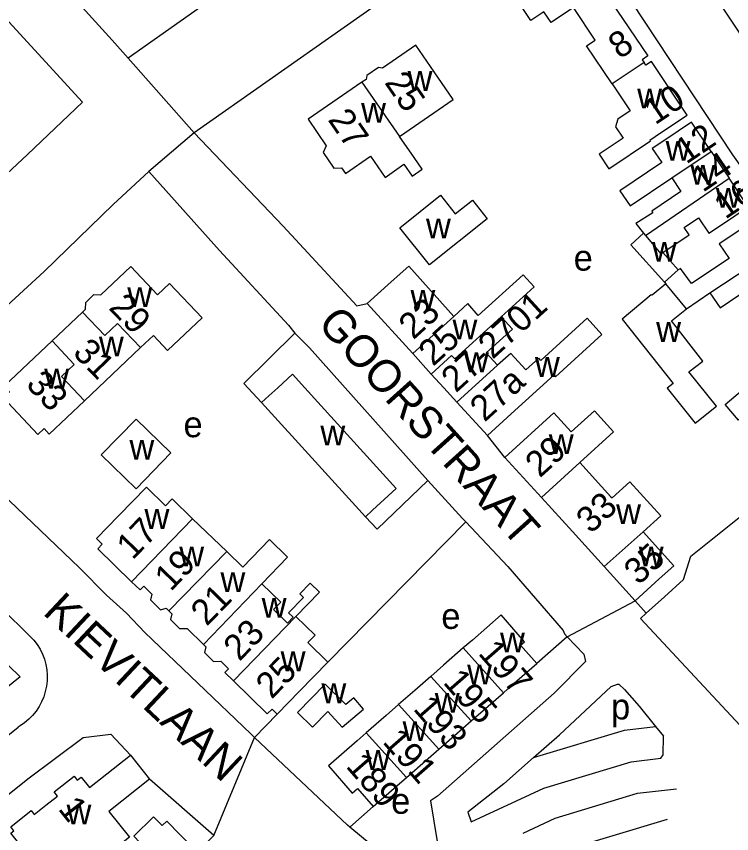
# Model space of a CAD drawing. Extents: x 161775 to 163181, y 382878 to 383925.
# Drawn here: x 162768.1 to 162879.2, y 383680.7 to 383807.7 of the extents above; entities that cross this region are included whole.
import ezdxf

# ---------------------------------------------------------------- set-up
doc = ezdxf.new("R2010")
doc.units = 0
for name, color, linetype in [('BLT_Basislijn', 7, 'Continuous'), ('BLT_Bebouwing', 7, 'Continuous'), ('BLT_Centroide', 7, 'Continuous'), ('BLT_Huisnummer', 7, 'Continuous'), ('BLT_Huisnummer_ tussenligend', 7, 'Continuous'), ('BLT_Huisnummer_reeks', 7, 'Continuous'), ('BLT_Onderverdeling_panden', 7, 'Continuous'), ('BLT_Straatnaam', 7, 'Continuous'), ('BLT_Vlakafsluiter', 7, 'Continuous')]:
    doc.layers.add(name, color=color, linetype=linetype)

msp = doc.modelspace()

# ---------------------------------------------------------------- linework, layer by layer
at = {"layer": 'BLT_Basislijn'}
for p, q in [((162844.02, 383739.18), (162841.29, 383742.56)), ((162745.28, 383735.94), (162770.85, 383710.77)), ((162837.92, 383729.15), (162816.52, 383707.36)), ((162768.72, 383705.07), (162755.35, 383717.89)), ((162865.98, 383714.96), (162864.26, 383716.91)), ((162853.7, 383711.28), (162848.95, 383707.13)), ((162768.72, 383705.07), (162747.45, 383688.05)), ((162805.12, 383695.66), (162808.63, 383699.27)), ((162712.92, 383652.82), (162768.39, 383697.27)), ((162798.8, 383680.44), (162788.81, 383689.19)), ((162823.55, 383684.9), (162819.92, 383681.73)), ((162850.56, 383677.36), (162869.25, 383682.97))]:
    msp.add_line(p, q, dxfattribs=at)
for points in [[(162703.8, 383876.24), (162706.56, 383872.66), (162712.77, 383866.28), (162715.7, 383862.52), (162731.68, 383845.59), (162737.91, 383838.46), (162738.87, 383837.6), (162741.07, 383834.89), (162742.28, 383833.77), (162778.38, 383794.39)], [(162785.46, 383801.22), (162782.97, 383804.02), (162724.1, 383868.83)], [(162843.74, 383842.12), (162840.57, 383839.67), (162820.94, 383826.15), (162818.33, 383824.15), (162805.7, 383815.51), (162785.46, 383801.22)], [(162624.33, 383833.08), (162626.77, 383831.18), (162649.91, 383815.03), (162662.77, 383805.45), (162714.41, 383769.18), (162720.06, 383764.71), (162723.13, 383762.72), (162734.54, 383754.59), (162735.88, 383754.49), (162750.82, 383768.72), (162752.99, 383770.53), (162769.85, 383786.24), (162778.38, 383794.39)], [(162862.81, 383831.51), (162863.53, 383830.66), (162880.56, 383804.94)], [(162851.26, 383828.4), (162847.79, 383826.29), (162838.22, 383819.22), (162830.67, 383814.23), (162795.74, 383789.61)], [(162851.26, 383828.4), (162861.71, 383812.99), (162879.37, 383786.19), (162884.88, 383778.46), (162900.37, 383755.32), (162903.33, 383751.28), (162915.73, 383733.22)], [(162795.74, 383789.61), (162809.57, 383775.09), (162821.01, 383762.71), (162822.63, 383763.09)], [(162805.12, 383695.66), (162804.54, 383696.2), (162788.08, 383711.95), (162785.2, 383714.99), (162782.12, 383717.76), (162777.9, 383722), (162751.13, 383747.61), (162751.03, 383747.93), (162760.8, 383757.39), (162772.45, 383768.09), (162783.14, 383778.49), (162788.71, 383783.59)], [(162788.71, 383783.59), (162799.68, 383771.31), (162810.39, 383759.71), (162811.35, 383758.46)], [(162806.21, 383747.71), (162803.43, 383750.68), (162811.35, 383758.46)], [(162811.35, 383758.46), (162813.67, 383756.2), (162832.06, 383735.59)], [(162822.33, 383729.96), (162824.19, 383728.03), (162832.06, 383735.59)], [(162837.92, 383729.15), (162837.44, 383729.66), (162832.06, 383735.59)], [(162837.92, 383729.15), (162844.46, 383722.2), (162853.05, 383712.28), (162853.25, 383711.74), (162853.7, 383711.28)], [(162853.7, 383711.28), (162856.29, 383708.62), (162856.52, 383707.48), (162851.68, 383702.53), (162833.55, 383686.54), (162832.46, 383685.79), (162833.5, 383679.47), (162828.96, 383677.8), (162826.05, 383677.67), (162823.21, 383678.95), (162819.92, 383681.73)], [(162770.85, 383710.77), (162771.35, 383710.1), (162771.8, 383709.37), (162772.17, 383708.61), (162772.46, 383707.82), (162772.69, 383707), (162772.83, 383706.16), (162772.9, 383705.32), (162772.88, 383704.47), (162772.79, 383703.63), (162772.61, 383702.8), (162772.36, 383701.99), (162772.03, 383701.21), (162771.64, 383700.46), (162771.17, 383699.75), (162770.64, 383699.09), (162770.04, 383698.49), (162769.4, 383697.94), (162768.7, 383697.45), (162768.39, 383697.27)], [(162848.46, 383692.52), (162852.49, 383696.08), (162860.53, 383703.55), (162861.48, 383703.93), (162861.7, 383703.96), (162862.6, 383703.1), (162864.87, 383700.54), (162867.43, 383697.37)], [(162848.46, 383692.52), (162862.58, 383696.81), (162867.43, 383697.37)], [(162867.43, 383697.37), (162868.64, 383695.86)], [(162626.44, 383574.02), (162637.05, 383582.56), (162638.49, 383583.91), (162653.34, 383595.54), (162654.82, 383596.89), (162659.77, 383600.62), (162668.36, 383607.94), (162675.68, 383613.76), (162684.73, 383621.34), (162722.73, 383651.25), (162727.65, 383655.52), (162732.82, 383659.35), (162734.51, 383660.88), (162769.87, 383689.21), (162778.48, 383695.66), (162782.77, 383696.15), (162785.83, 383692.92)], [(162819.92, 383681.73), (162819.56, 383682.03), (162805.12, 383695.66)], [(162868.25, 383692.44), (162868.59, 383692.95), (162868.64, 383695.86)], [(162838.76, 383682.55), (162850.04, 383687.77), (162863.61, 383691.89), (162868.25, 383692.44)], [(162843.83, 383688.42), (162848.46, 383692.52)], [(162843.83, 383688.42), (162838.27, 383684.03), (162838.76, 383682.55)], [(162846.83, 383680.77), (162851.83, 383683.09), (162864.63, 383686.98), (162870.66, 383687.68)]]:
    msp.add_lwpolyline(points, dxfattribs=at)
at = {"layer": 'BLT_Bebouwing'}
for p, q in [((162876.05, 383786.72), (162878.84, 383782.56)), ((162863.57, 383772.22), (162865.56, 383774.04)), ((162868.52, 383771.02), (162870.95, 383768.33)), ((162822.63, 383763.09), (162829.68, 383755.3)), ((162773.65, 383757.27), (162778.41, 383761.77)), ((162829.68, 383755.3), (162832.56, 383752.13)), ((162806.21, 383747.71), (162822.33, 383729.96)), ((162836.55, 383747.74), (162841.29, 383742.56)), ((162849.67, 383732.96), (162844.02, 383739.18)), ((162855.65, 383738.39), (162860.49, 383733.07)), ((162854.5, 383727.65), (162849.67, 383732.96)), ((162859.44, 383722.22), (162854.5, 383727.65)), ((162864.26, 383716.91), (162859.44, 383722.22)), ((162838.95, 383710.79), (162837.55, 383709.56)), ((162837.55, 383709.56), (162834.48, 383706.88)), ((162834.48, 383706.88), (162832.51, 383705.15)), ((162845.1, 383703.76), (162848.95, 383707.13)), ((162832.51, 383705.15), (162830.01, 383702.96)), ((162843.78, 383702.61), (162845.1, 383703.76)), ((162830.01, 383702.96), (162827.5, 383700.77)), ((162840.63, 383699.85), (162843.78, 383702.61)), ((162827.5, 383700.77), (162825.54, 383699.05)), ((162838.76, 383698.22), (162840.63, 383699.85)), ((162825.54, 383699.05), (162822.48, 383696.37)), ((162836.16, 383695.94), (162838.76, 383698.22)), ((162822.48, 383696.37), (162821.07, 383695.14)), ((162833.74, 383693.82), (162836.16, 383695.94)), ((162831.69, 383692.03), (162833.74, 383693.82)), ((162785.83, 383692.92), (162788.81, 383689.19)), ((162828.71, 383689.42), (162831.69, 383692.03)), ((162827.22, 383688.11), (162828.71, 383689.42)), ((162823.55, 383684.9), (162827.22, 383688.11))]:
    msp.add_line(p, q, dxfattribs=at)
for points in [[(162860.66, 383797.25), (162856.7, 383803.15), (162858.03, 383804.04), (162854.65, 383809.08), (162851.2, 383806.76), (162850.08, 383808.42), (162848.05, 383807.06), (162845.06, 383811.52), (162842.27, 383815.67), (162849.89, 383820.78), (162851.18, 383818.84), (162852.52, 383819.74), (162857.54, 383812.25), (162858.57, 383812.94), (162866.2, 383801.56), (162865.34, 383800.98), (162865.62, 383800.55)], [(162827.64, 383789.07), (162835.98, 383794.8), (162833.02, 383799.1), (162830.19, 383803.22), (162824.98, 383799.64), (162824.35, 383799.76), (162822.54, 383798.52), (162822.43, 383797.92), (162821.79, 383797.48)], [(162860.66, 383797.25), (162863.49, 383793.04), (162861.54, 383791.73), (162861.18, 383790.55), (162862.37, 383788.78), (162858.64, 383786.29), (162860.16, 383784.03), (162866.61, 383788.35), (162866.52, 383788.49), (162868.17, 383789.59), (162872.32, 383792.38), (162866.78, 383800.68), (162865.91, 383800.11), (162865.62, 383800.55)], [(162821.79, 383797.48), (162813.43, 383791.73), (162816.26, 383787.62), (162815.75, 383786.54), (162817.42, 383784.1), (162818.62, 383784.19), (162819.24, 383783.29), (162823.13, 383785.97), (162825.4, 383782.67), (162828.31, 383784.75), (162829.61, 383782.87), (162831.17, 383783.95), (162829.91, 383785.77), (162827.64, 383789.07)], [(162876.05, 383786.72), (162872.99, 383791.28), (162868.84, 383788.5), (162866.91, 383787.18), (162868.4, 383784.99), (162861.88, 383780.62), (162863.45, 383778.27), (162869.93, 383782.61)], [(162869.93, 383782.61), (162871.35, 383780.49), (162866.81, 383777.44), (162866.99, 383777.17), (162864.33, 383775.52), (162865.56, 383774.04)], [(162868.52, 383771.02), (162872.62, 383773.76), (162871.84, 383774.91), (162874.09, 383776.42), (162875.7, 383774.02), (162877.66, 383775.34), (162881.82, 383778.12), (162878.84, 383782.56)], [(162886.2, 383771.65), (162884.86, 383773.64), (162885.38, 383773.99), (162883.9, 383776.21), (162883.37, 383775.85), (162883.11, 383776.24), (162878.96, 383773.45), (162877.32, 383772.37), (162878.83, 383770.09), (162873.01, 383766.19), (162871.3, 383768.54), (162870.95, 383768.33)], [(162863.57, 383772.22), (162868.82, 383766.39)], [(162875.87, 383764.73), (162877.43, 383762.4), (162881.98, 383765.46), (162883.49, 383763.22), (162885.11, 383764.29), (162889.27, 383767.08), (162886.2, 383771.65)], [(162778.41, 383761.77), (162778.86, 383762.2), (162778.89, 383763.27), (162780.17, 383764.48), (162781.24, 383764.45), (162785.88, 383768.84), (162790.04, 383764.43), (162791.91, 383766.2), (162796.96, 383760.89), (162791.59, 383755.81), (162789.4, 383758.12), (162787.42, 383756.24)], [(162836.05, 383761.09), (162829.07, 383768.92), (162826.34, 383766.44), (162822.63, 383763.09)], [(162843.44, 383761.02), (162848.55, 383765.67), (162846.84, 383767.56), (162839.88, 383761.25), (162838.23, 383763.08), (162836.05, 383761.09)], [(162869.03, 383766.14), (162866.89, 383764.38), (162866.74, 383764.42), (162862.25, 383760.68), (162870.17, 383750.68), (162869.23, 383749.93), (162873.57, 383744.5), (162876.86, 383747.13), (162872.6, 383752.46), (162874.77, 383754.15), (162869.9, 383760.38), (162872.2, 383762.26)], [(162868.82, 383766.39), (162869.03, 383766.14)], [(162872.2, 383762.26), (162875.87, 383764.73)], [(162843.44, 383761.02), (162845.18, 383759.1), (162843.16, 383757.27), (162841.12, 383755.42), (162842.87, 383753.49)], [(162841.29, 383742.56), (162844.99, 383745.93), (162849.45, 383750), (162851.64, 383751.99), (162851.89, 383751.72), (162859.09, 383758.25), (162856.77, 383760.8), (162849.58, 383754.26), (162849.27, 383754.61), (162847.24, 383752.77), (162844.91, 383755.34), (162842.87, 383753.49)], [(162778.68, 383747.99), (162773.21, 383742.81), (162772.42, 383743.65), (162771.47, 383742.76), (162766.08, 383748.47), (162767.03, 383749.36), (162766.42, 383750), (162766.2, 383750.23), (162773.65, 383757.27)], [(162778.68, 383747.99), (162780.8, 383750), (162787.42, 383756.24)], [(162887.66, 383745.68), (162885.02, 383748.94), (162880.31, 383744.94), (162878.22, 383747.41), (162886.6, 383754.51), (162887.68, 383755.24), (162887.46, 383755.36)], [(162822.33, 383729.96), (162823.44, 383730.96), (162827.14, 383734.33), (162812.92, 383750), (162811.02, 383752.09), (162808.72, 383750), (162807.32, 383748.73), (162806.21, 383747.71)], [(162832.56, 383752.13), (162834.5, 383749.99), (162836.55, 383747.74)], [(162844.02, 383739.18), (162851.62, 383746.1), (162854.32, 383743.13), (162857.92, 383746.41), (162860.89, 383743.15), (162855.65, 383738.39)], [(162860.49, 383733.07), (162860.67, 383732.87), (162863.42, 383735.38), (162868.22, 383730.09), (162865.47, 383727.59)], [(162795.48, 383729.63), (162792.31, 383732.72), (162791.28, 383731.66), (162788.32, 383734.54), (162784.04, 383730.15), (162780.55, 383726.57), (162781.46, 383725.68), (162780.77, 383724.97), (162786.02, 383719.86)], [(162865.98, 383714.96), (162868.78, 383717.51), (162871.76, 383720.22), (162872.87, 383723.81), (162882.71, 383731.71)], [(162795.48, 383729.63), (162800.81, 383724.55)], [(162865.47, 383727.59), (162870.24, 383722.35), (162867.96, 383720.28), (162864.26, 383716.91)], [(162800.81, 383724.55), (162803.27, 383722.14), (162807.43, 383726.4), (162810.24, 383723.65), (162806.23, 383719.55)], [(162786.02, 383719.86), (162787.34, 383718.57), (162787.89, 383719.14), (162789.16, 383717.91), (162788.93, 383717.02), (162790.48, 383715.5), (162791.39, 383715.76), (162791.82, 383715.33)], [(162806.23, 383719.55), (162809.18, 383716.66), (162808.07, 383715.52), (162810.21, 383713.43), (162811.1, 383714.35), (162810.4, 383715.03), (162812.72, 383717.4), (162812.14, 383717.97), (162813.77, 383719.64), (162815.22, 383718.23), (162811.54, 383714.46)], [(162791.82, 383715.33), (162792.29, 383714.88), (162792.06, 383713.97), (162793.48, 383712.58), (162794.64, 383712.59), (162797.21, 383710.08)], [(162811.54, 383714.46), (162814.51, 383711.56), (162813.39, 383710.41), (162816.52, 383707.36)], [(162848.95, 383707.13), (162846.45, 383709.98), (162847.07, 383710.52), (162843.42, 383714.7), (162838.95, 383710.79)], [(162883.88, 383694.79), (162883.34, 383694.51), (162865.08, 383714.14), (162865.98, 383714.96)], [(162797.21, 383710.08), (162797.57, 383709.74), (162797.34, 383708.83), (162798.74, 383707.47), (162799.9, 383707.49), (162801.07, 383706.34), (162800.49, 383705.74), (162801.84, 383704.43)], [(162808.63, 383699.27), (162812.12, 383702.85), (162816.52, 383707.36)], [(162801.84, 383704.43), (162807.09, 383699.3), (162807.83, 383700.05), (162808.63, 383699.27)], [(162811.8, 383699.51), (162814.14, 383697.25), (162816.48, 383699.67), (162818.74, 383697.25), (162822.02, 383700.06), (162820.53, 383701.81), (162819.31, 383700.77), (162816.09, 383703.91), (162811.8, 383699.51)], [(162821.07, 383695.14), (162816.6, 383691.23), (162820.3, 383687), (162821.1, 383687.7), (162823.55, 383684.9)], [(162772.7, 383685.11), (162774.51, 383686.55), (162774.01, 383687.18), (162777.07, 383689.62), (162777.56, 383689.02), (162778.17, 383689.5), (162779.48, 383687.86), (162785.83, 383692.92)], [(162788.81, 383689.19), (162782.49, 383684.15), (162785.68, 383680.16), (162781.77, 383677.04), (162780.16, 383675.75)], [(162770.37, 383669.19), (162767.38, 383673.06), (162771.11, 383675.95), (162767.27, 383680.77), (162767.74, 383681.15), (162767.24, 383681.78), (162770.39, 383684.29), (162770.89, 383683.67), (162772.7, 383685.11)], [(162798.8, 383680.44), (162797.58, 383679.25), (162799.12, 383677.68), (162797.69, 383676.28), (162791.47, 383682.65), (162790.75, 383681.95), (162789.43, 383683.31), (162786.37, 383680.32), (162802.45, 383663.3), (162803.49, 383664.28), (162805.75, 383661.89)]]:
    msp.add_lwpolyline(points, dxfattribs=at)
for points in [[(162827.68, 383774.87), (162834.02, 383779.91), (162836.3, 383777.04), (162838.95, 383779.15), (162841.27, 383776.23), (162832.28, 383769.09)], [(162786.71, 383745.13), (162792.11, 383739.86), (162786.7, 383734.31), (162781.29, 383739.58)]]:
    msp.add_lwpolyline(points, close=True, dxfattribs=at)
at = {"layer": 'BLT_Onderverdeling_panden'}
for p, q in [((162865.62, 383800.55), (162860.66, 383797.25)), ((162821.79, 383797.48), (162827.64, 383789.07)), ((162869.93, 383782.61), (162876.05, 383786.72)), ((162865.87, 383773.66), (162878.84, 383782.56)), ((162865.56, 383774.04), (162865.87, 383773.66)), ((162875.87, 383764.73), (162886.2, 383771.65)), ((162868.82, 383766.39), (162870.95, 383768.33)), ((162872.2, 383762.26), (162869.03, 383766.14)), ((162836.05, 383761.09), (162829.68, 383755.3)), ((162842.87, 383753.49), (162836.55, 383747.74)), ((162849.67, 383732.96), (162855.65, 383738.39)), ((162795.48, 383729.63), (162786.02, 383719.86)), ((162859.44, 383722.22), (162865.47, 383727.59)), ((162800.81, 383724.55), (162791.82, 383715.33)), ((162806.23, 383719.55), (162797.21, 383710.08)), ((162811.54, 383714.46), (162801.84, 383704.43)), ((162843.78, 383702.61), (162837.55, 383709.56)), ((162838.76, 383698.22), (162832.51, 383705.15)), ((162833.74, 383693.82), (162827.5, 383700.77)), ((162828.71, 383689.42), (162822.48, 383696.37))]:
    msp.add_line(p, q, dxfattribs=at)
for points in [[(162865.87, 383773.66), (162868.23, 383770.82), (162868.52, 383771.02)], [(162787.42, 383756.24), (162783.82, 383759.97), (162781.86, 383758.12), (162778.41, 383761.77)], [(162843.44, 383761.02), (162836.23, 383754.47), (162835.73, 383755.02), (162832.56, 383752.13)], [(162778.68, 383747.99), (162775.15, 383751.75), (162777.11, 383753.61), (162773.65, 383757.27)]]:
    msp.add_lwpolyline(points, dxfattribs=at)
at = {"layer": 'BLT_Vlakafsluiter'}
for p, q in [((162785.46, 383801.22), (162795.74, 383789.61)), ((162795.74, 383789.61), (162788.71, 383783.59)), ((162853.7, 383711.28), (162864.26, 383716.91)), ((162798.8, 383680.44), (162805.12, 383695.66))]:
    msp.add_line(p, q, dxfattribs=at)

# ---------------------------------------------------------------- texts
at = {"layer": 'BLT_Centroide'}
for s, p in [('w', (162828.89, 383796.14)), ('w', (162864.56, 383793.41)), ('w', (162821.67, 383791.19)), ('w', (162868.97, 383785.28)), ('w', (162872.83, 383781.55)), ('w', (162876.78, 383777.97)), ('w', (162831.75, 383773.2)), ('w', (162866.85, 383769.59)), ('e', (162854.69, 383768.2)), ('w', (162785.35, 383762.53)), ('w', (162829.34, 383762.14)), ('w', (162835.87, 383757.53)), ('w', (162867.51, 383757.13)), ('w', (162780.94, 383754.88)), ('w', (162837.65, 383752.42)), ('w', (162848.67, 383751.69)), ('w', (162772.44, 383749.88)), ('e', (162794.08, 383742.31)), ('w', (162815.34, 383741.03)), ('w', (162785.68, 383738.83)), ('w', (162850.83, 383739.69)), ('w', (162861.29, 383728.81)), ('w', (162788.02, 383728.06)), ('w', (162793.42, 383722.23)), ('w', (162864.8, 383722.25)), ('w', (162799.82, 383718.25)), ('w', (162806.22, 383714.25)), ('e', (162834.13, 383712.52)), ('w', (162843.25, 383708.88)), ('w', (162809.17, 383705.94)), ('w', (162838.14, 383703.91)), ('w', (162815.5, 383700.98)), ('w', (162833.12, 383699.48)), ('p', (162860.5, 383698.45)), ('w', (162828.11, 383695.09)), ('w', (162822.37, 383690.62)), ('e', (162826.34, 383683.79)), ('w', (162775.91, 383682.16))]:
    msp.add_text(s, height=4, dxfattribs=at).set_placement(p)
at = {"layer": 'BLT_Huisnummer'}
for s, rotation, p in [('25', 304.5232, (162825.21, 383797.42)), ('10', 33.8517, (162867.35, 383790.76)), ('27', 304.5174, (162816.41, 383791.65)), ('12', 33.8517, (162872.18, 383784.66)), ('14', 33.8427, (162874.75, 383780.28)), ('16', 33.8427, (162878.25, 383776.09)), ('29', 314.0783, (162782.32, 383762.32)), ('23', 42.2845, (162829.78, 383757.35)), ('33', 313.3733, (162769.45, 383750.39)), ('27a', 42.3739, (162840.85, 383744.56)), ('29', 42.2799, (162849.43, 383735.89)), ('17', 45.7212, (162786.15, 383723.11)), ('35', 42.2852, (162864.77, 383719.21)), ('21', 45.7199, (162797.68, 383712.83)), ('197', 311.1877, (162839.73, 383708.67)), ('25', 45.7129, (162807.78, 383701.5)), ('193', 311.1917, (162829.63, 383700.04)), ('189', 311.1898, (162819.17, 383691.12)), ('1', 308.5813, (162774.48, 383684.53))]:
    msp.add_text(s, height=4, rotation=rotation, dxfattribs=at).set_placement(p)
at = {"layer": 'BLT_Huisnummer_ tussenligend'}
for s, rotation, p in [('25', 42.1781, (162832.85, 383753.22)), ('31', 314.0783, (162776.72, 383755.3)), ('33', 42.2794, (162857.35, 383727.19)), ('19', 45.7212, (162792.07, 383718.22)), ('23', 45.7199, (162802.76, 383707.36)), ('195', 311.1917, (162834.26, 383704.15)), ('191', 311.1898, (162824.87, 383694.9))]:
    msp.add_text(s, height=4, rotation=rotation, dxfattribs=at).set_placement(p)
at = {"layer": 'BLT_Huisnummer_reeks'}
for s, rotation, p in [('8', 33.8517, (162861.83, 383800.98)), ('27-2701', 42.3739, (162836.4, 383749.11))]:
    msp.add_text(s, height=4, rotation=rotation, dxfattribs=at).set_placement(p)
at = {"layer": 'BLT_Straatnaam'}
for s, rotation, p in [('GOORSTRAAT', 311.9866, (162814.74, 383759.83)), ('KIEVITLAAN', 316.8203, (162772.07, 383714.93))]:
    msp.add_text(s, height=5, rotation=rotation, dxfattribs=at).set_placement(p)

doc.saveas('drawing.dxf')
